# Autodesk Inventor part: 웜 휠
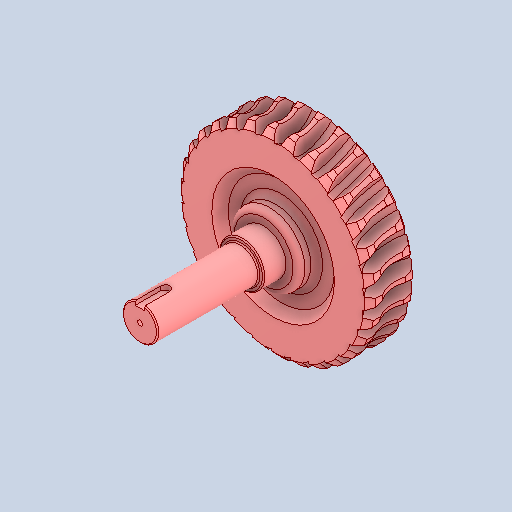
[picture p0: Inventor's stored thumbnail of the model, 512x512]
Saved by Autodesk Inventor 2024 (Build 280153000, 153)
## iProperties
Created: 2025-05
Part Number: 웜 휠
Material: 탄소강
Document SubType Name: Modeling
Designer: 11
Density: 7.87 g/cm^3
Appearance: 기본값
Author: jhkim
Sending System: Autodesk Inventor 2026
Preprocessor: ST-DEVELOPER v20.1
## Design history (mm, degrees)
node "웜 휠1"
node "솔리드1"
body "Solid1"
